(* Logix 5000 project; controller Hardy_1769_Sample_Program vendor 1 type 14 code 151 rev 30.11; software revision 30.02; part 5 of 5 *)
(* tags used below, declared in another part *)
   Control_Bits : BOOL[32];   // Control Bits For All Routines In This Program
   Current_Metric : INT;   // Current Metric Settings
   Default_Return_Flt : HardyFloatWeight;   // Default Return Values With Weight In Foating Point Format
   Default_Return_Int : HardyIntWeight;   // Default Return Values With Weight In Integer Format
   Error_Flag : BOOL;
   Metric : INT;   // New Metric Setting
   Motion : BOOL;
   One_Shot : BOOL[32];   // One Shots For Program Control
   Status_Return : HardyCmdResult;   // Command Status Returned
(* Hardy_HI1769_Scale_1, continued *)

ROUTINE Write_to_Non_Volatile   (* ladder *)
// SAVE CURRENT SETTINGS TO NON VOLATILE MEMORY
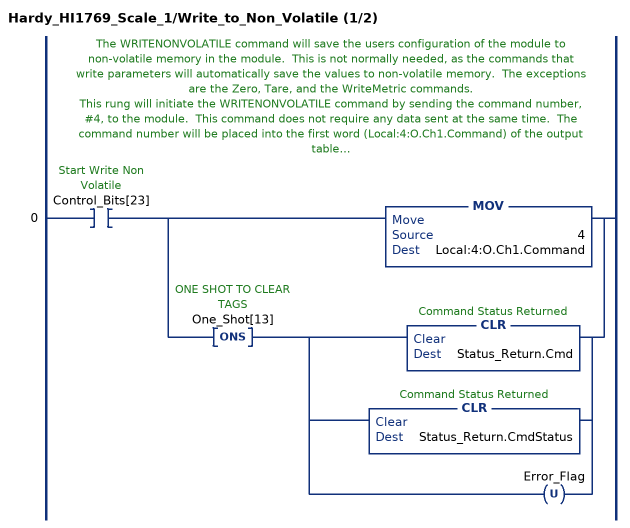
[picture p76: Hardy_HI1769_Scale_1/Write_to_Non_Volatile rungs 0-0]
   // The WRITENONVOLATILE command will save the users configuration of the module to non-volatile memory in the module.  This is not normally needed, as the commands that write parameters will automatically save the values to non-volatile memory.  The exceptions are the Zero, Tare, and the WriteMetric commands.
   // This rung will initiate the WRITENONVOLATILE command by sending the command number, #4, to the module.  This command does not require any data sent at the same time.  The command number will be placed into the first word (Local:4:O.Ch1.Command) of the output table.
   // Here the program will also clear the Status_Return tag and ERROR_FLAG of any previous values before running this command and receiving its return values.
   0: XIC(Control_Bits[23])[MOV(4,Local:4:O.Ch1.Command) ,ONS(One_Shot[13]) [CLR(Status_Return.Cmd) ,CLR(Status_Return.CmdStatus) ,OTU(Error_Flag) ] ];
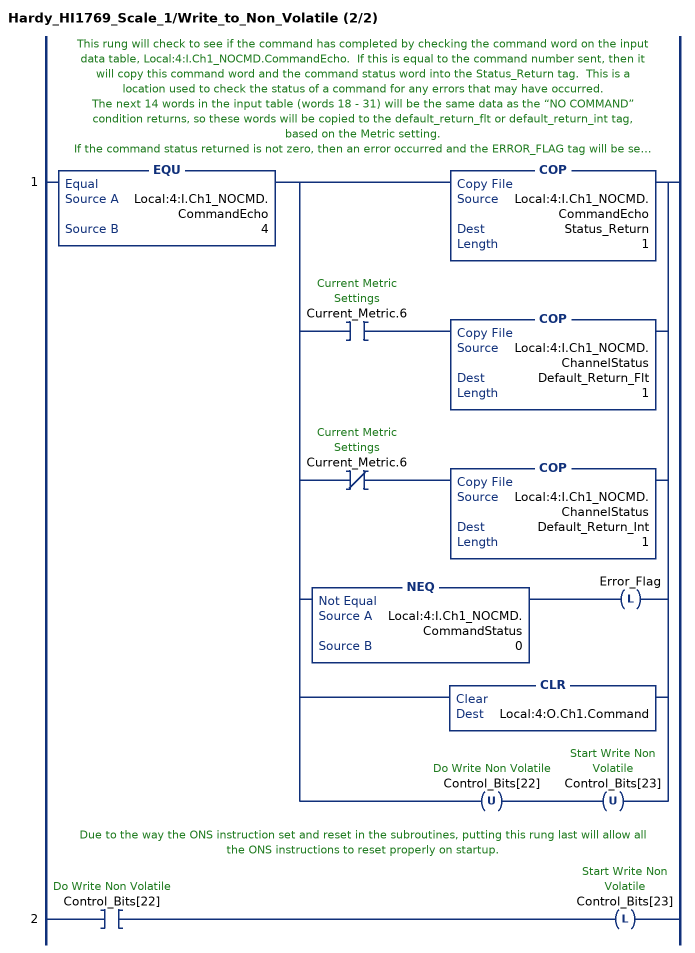
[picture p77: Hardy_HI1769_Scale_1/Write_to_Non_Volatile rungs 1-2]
   // This rung will check to see if the command has completed by checking the command word on the input data table, Local:4:I.Ch1_NOCMD.CommandEcho.  If this is equal to the command number sent, then it will copy this command word and the command status word into the Status_Return tag.  This is a location used to check the status of a command for any errors that may have occurred.
   // The next 14 words in the input table (words 18 - 31) will be the same data as the “NO COMMAND” condition returns, so these words will be copied to the default_return_flt or default_return_int tag, based on the Metric setting.
   // If the command status returned is not zero, then an error occurred and the ERROR_FLAG tag will be set high.  The user can monitor this bit to know if an error occurred and then check the Status_Return tag for the command and status return.
   // Finally, the command is cleared from the output table, Local:4:O.Ch1.Command, and any control bits are cleared.
   1: EQU(Local:4:I.Ch1_NOCMD.CommandEcho,4)[COP(Local:4:I.Ch1_NOCMD.CommandEcho,Status_Return,1) ,XIC(Current_Metric.6) COP(Local:4:I.Ch1_NOCMD.ChannelStatus,Default_Return_Flt,1) ,XIO(Current_Metric.6) COP(Local:4:I.Ch1_NOCMD.ChannelStatus,Default_Return_Int,1) ,NEQ(Local:4:I.Ch1_NOCMD.CommandStatus,0) OTL(Error_Flag) ,CLR(Local:4:O.Ch1.Command) ,OTU(Control_Bits[22]) OTU(Control_Bits[23]) ];
   // Due to the way the ONS instruction set and reset in the subroutines, putting this rung last will allow all the ONS instructions to reset properly on startup.
   2: XIC(Control_Bits[22])OTL(Control_Bits[23]);
END_ROUTINE

ROUTINE Zero   (* ladder *)
// ZERO THE CURRENT GROSS WEIGHT
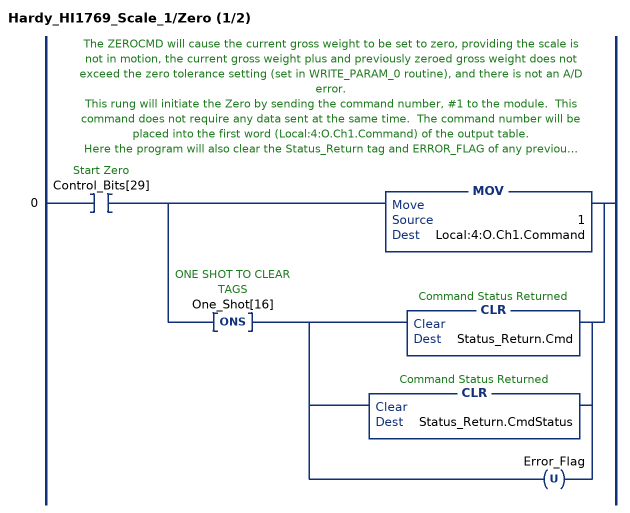
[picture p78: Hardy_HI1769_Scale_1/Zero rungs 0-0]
   // The ZEROCMD will cause the current gross weight to be set to zero, providing the scale is not in motion, the current gross weight plus and previously zeroed gross weight does not exceed the zero tolerance setting (set in WRITE_PARAM_0 routine), and there is not an A/D error.
   // This rung will initiate the Zero by sending the command number, #1 to the module.  This command does not require any data sent at the same time.  The command number will be placed into the first word (Local:4:O.Ch1.Command) of the output table.
   // Here the program will also clear the Status_Return tag and ERROR_FLAG of any previous values before running this command and receiving its return values.
   0: XIC(Control_Bits[29])[MOV(1,Local:4:O.Ch1.Command) ,ONS(One_Shot[16]) [CLR(Status_Return.Cmd) ,CLR(Status_Return.CmdStatus) ,OTU(Error_Flag) ] ];
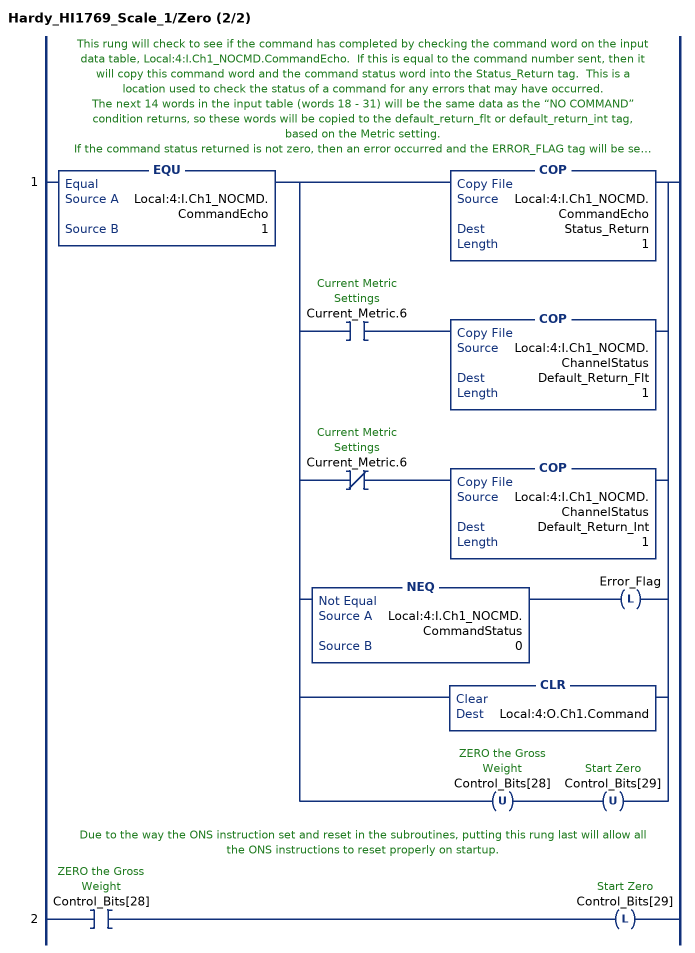
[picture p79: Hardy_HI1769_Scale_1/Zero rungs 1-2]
   // This rung will check to see if the command has completed by checking the command word on the input data table, Local:4:I.Ch1_NOCMD.CommandEcho.  If this is equal to the command number sent, then it will copy this command word and the command status word into the Status_Return tag.  This is a location used to check the status of a command for any errors that may have occurred.
   // The next 14 words in the input table (words 18 - 31) will be the same data as the “NO COMMAND” condition returns, so these words will be copied to the default_return_flt or default_return_int tag, based on the Metric setting.
   // If the command status returned is not zero, then an error occurred and the ERROR_FLAG tag will be set high.  The user can monitor this bit to know if an error occurred and then check the Status_Return tag for the command and status return.
   // Finally, the command is cleared from the output table, Local:4:O.Ch1.Command, and any control bits are cleared.
   1: EQU(Local:4:I.Ch1_NOCMD.CommandEcho,1)[COP(Local:4:I.Ch1_NOCMD.CommandEcho,Status_Return,1) ,XIC(Current_Metric.6) COP(Local:4:I.Ch1_NOCMD.ChannelStatus,Default_Return_Flt,1) ,XIO(Current_Metric.6) COP(Local:4:I.Ch1_NOCMD.ChannelStatus,Default_Return_Int,1) ,NEQ(Local:4:I.Ch1_NOCMD.CommandStatus,0) OTL(Error_Flag) ,CLR(Local:4:O.Ch1.Command) ,OTU(Control_Bits[28]) OTU(Control_Bits[29]) ];
   // Due to the way the ONS instruction set and reset in the subroutines, putting this rung last will allow all the ONS instructions to reset properly on startup.
   2: XIC(Control_Bits[28])OTL(Control_Bits[29]);
END_ROUTINE
END_PROGRAM
